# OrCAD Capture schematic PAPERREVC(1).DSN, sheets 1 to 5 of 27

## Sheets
1 PAGE1: title: SMART NETWORK ADC PROCESSOR (SNAP) BOARD; rev: C
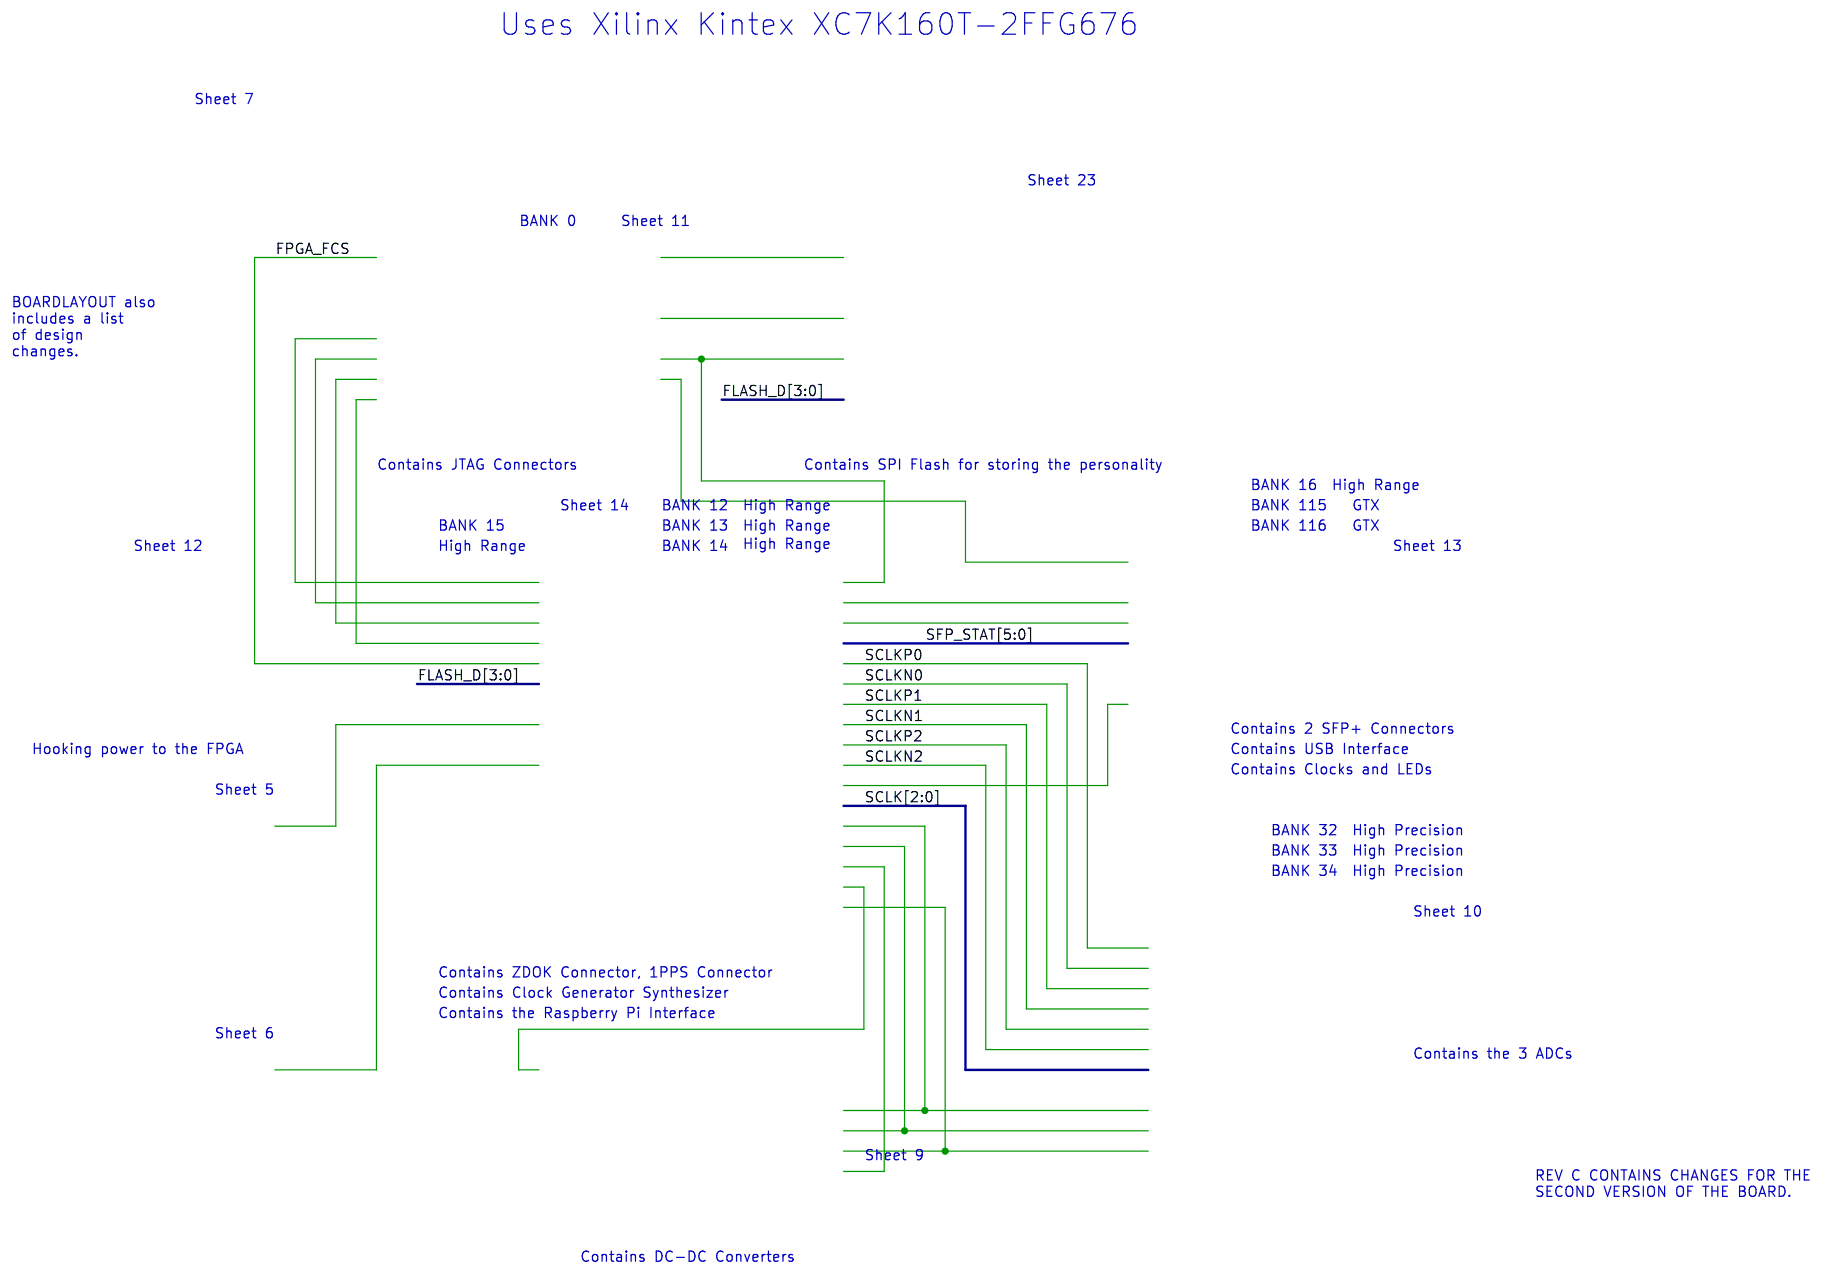
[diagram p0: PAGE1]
2 PAGE1 (2): size B; title: SNAP, JTAG and Bank 0; block FPGA0
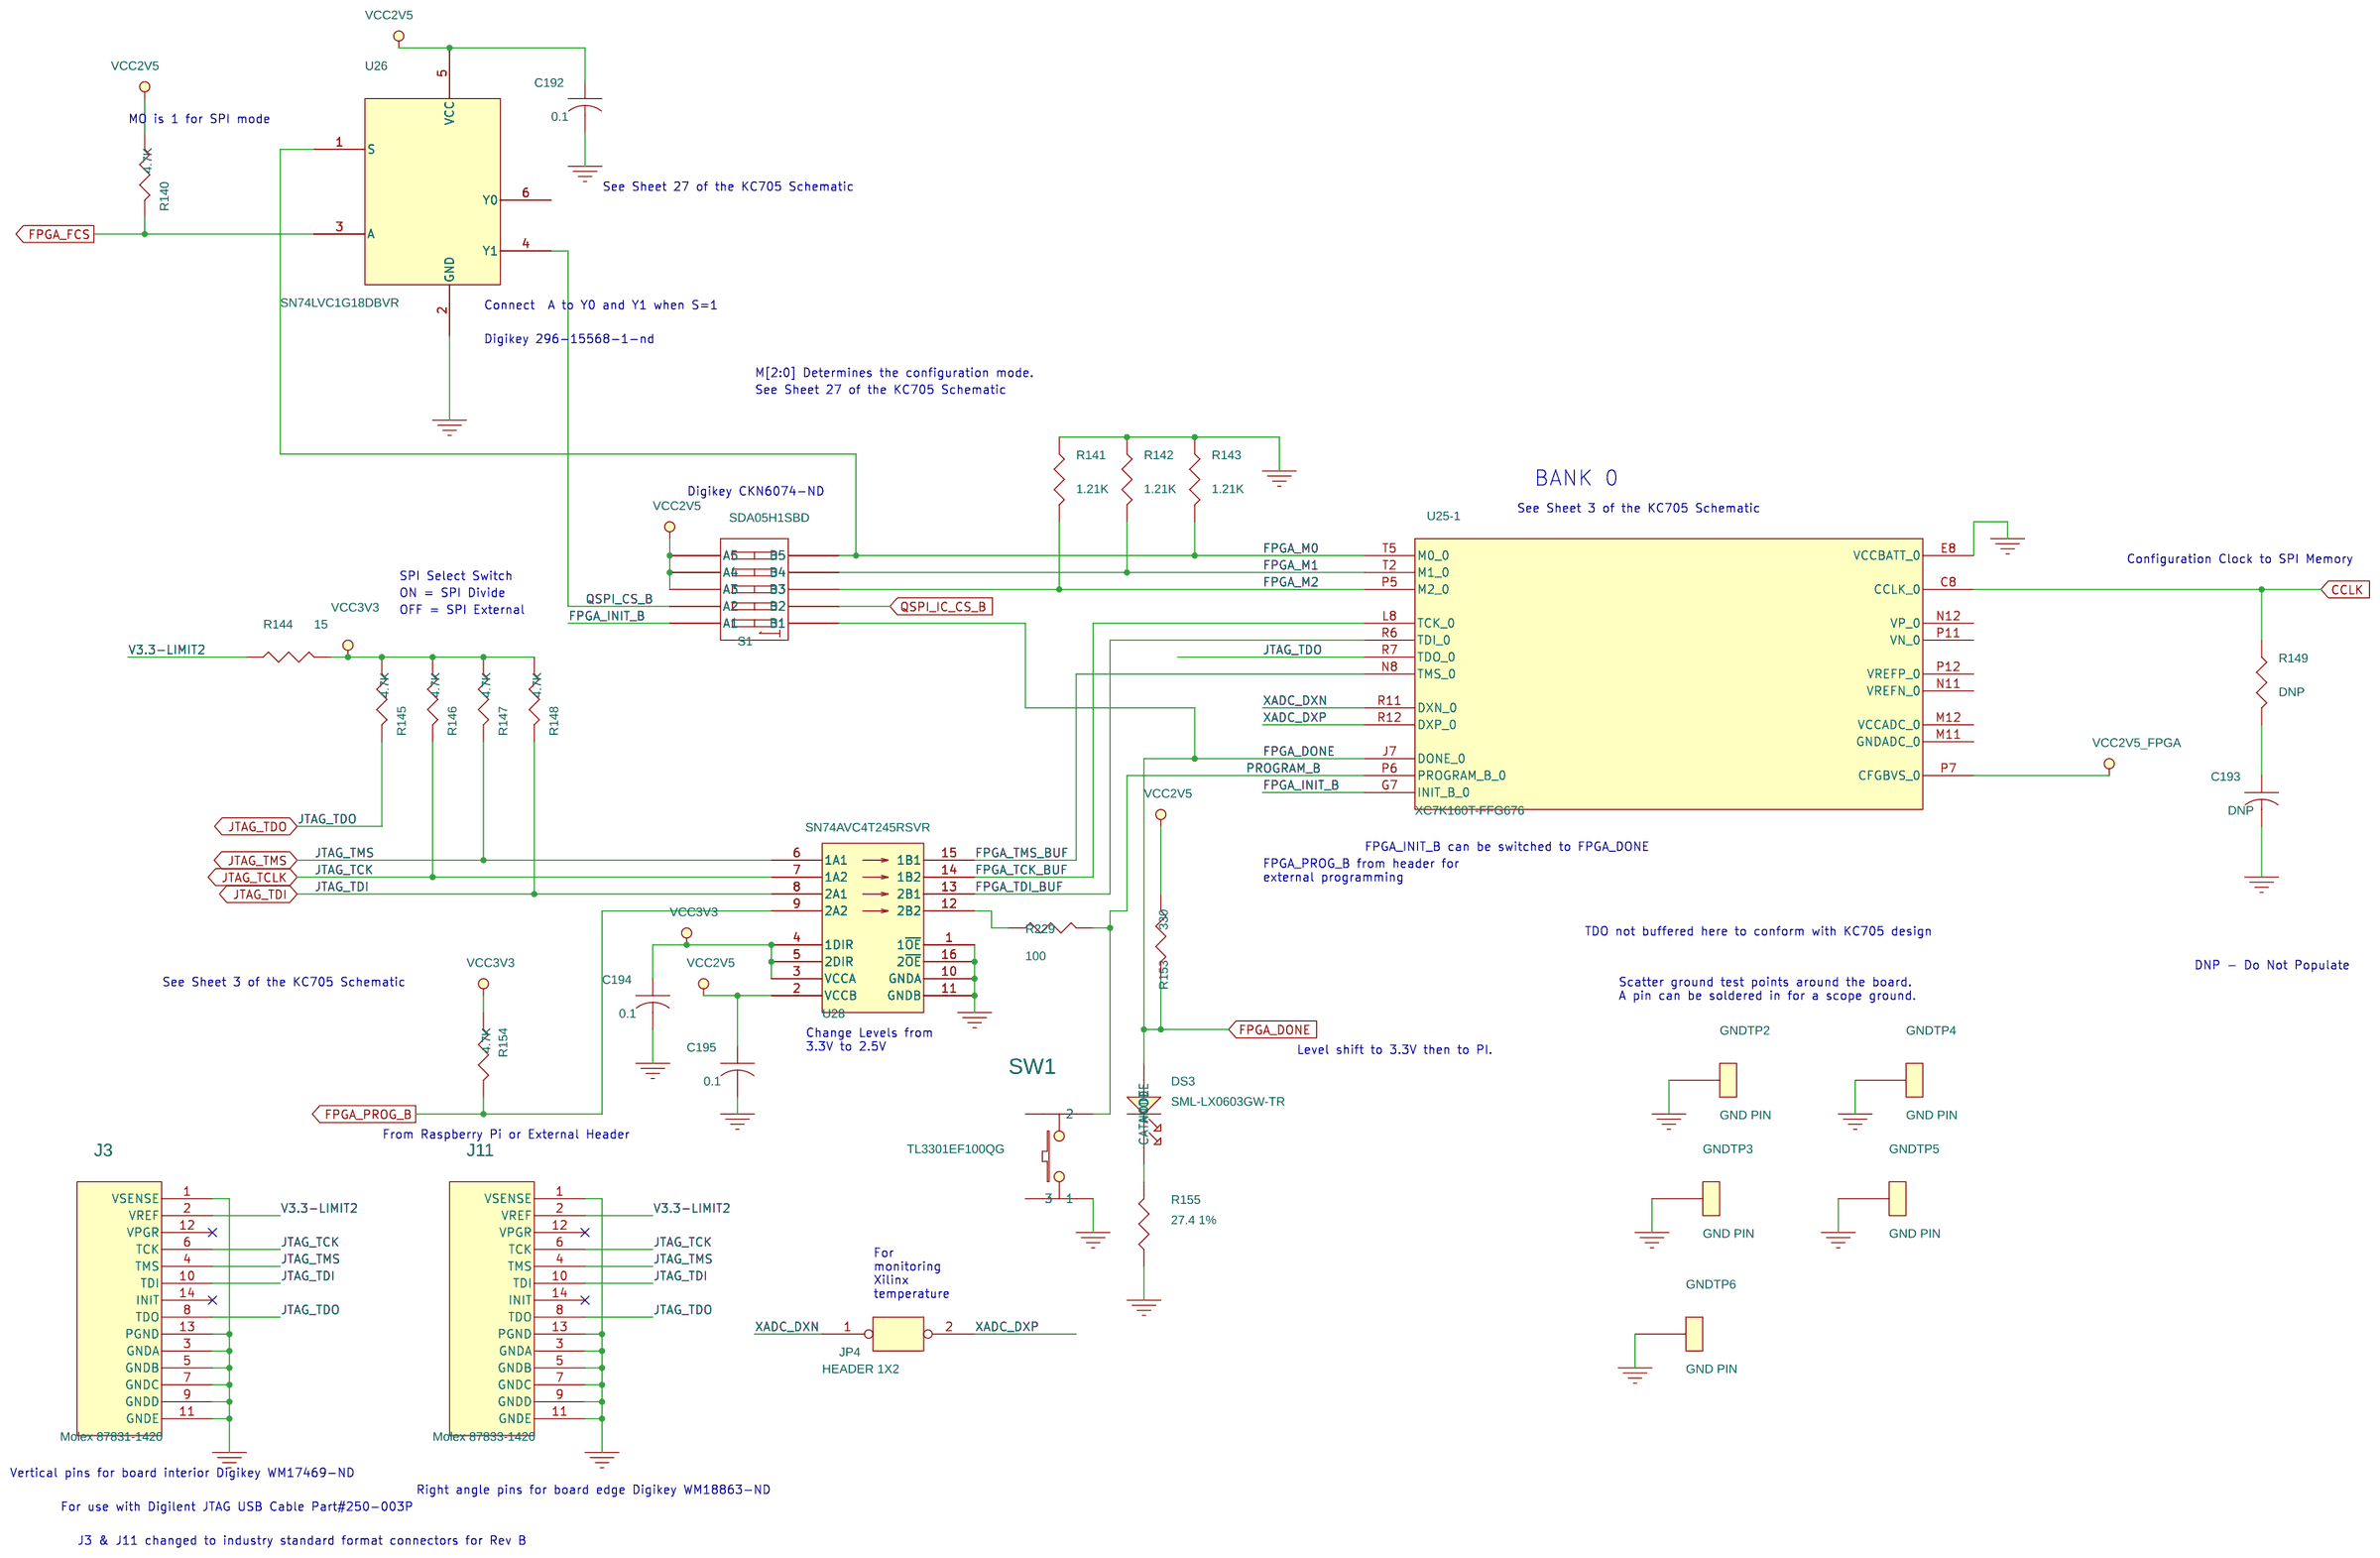
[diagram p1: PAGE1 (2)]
3 PAGE1 (3): size B; title: SNAP, A/D CONVERTERS; block FPGA32
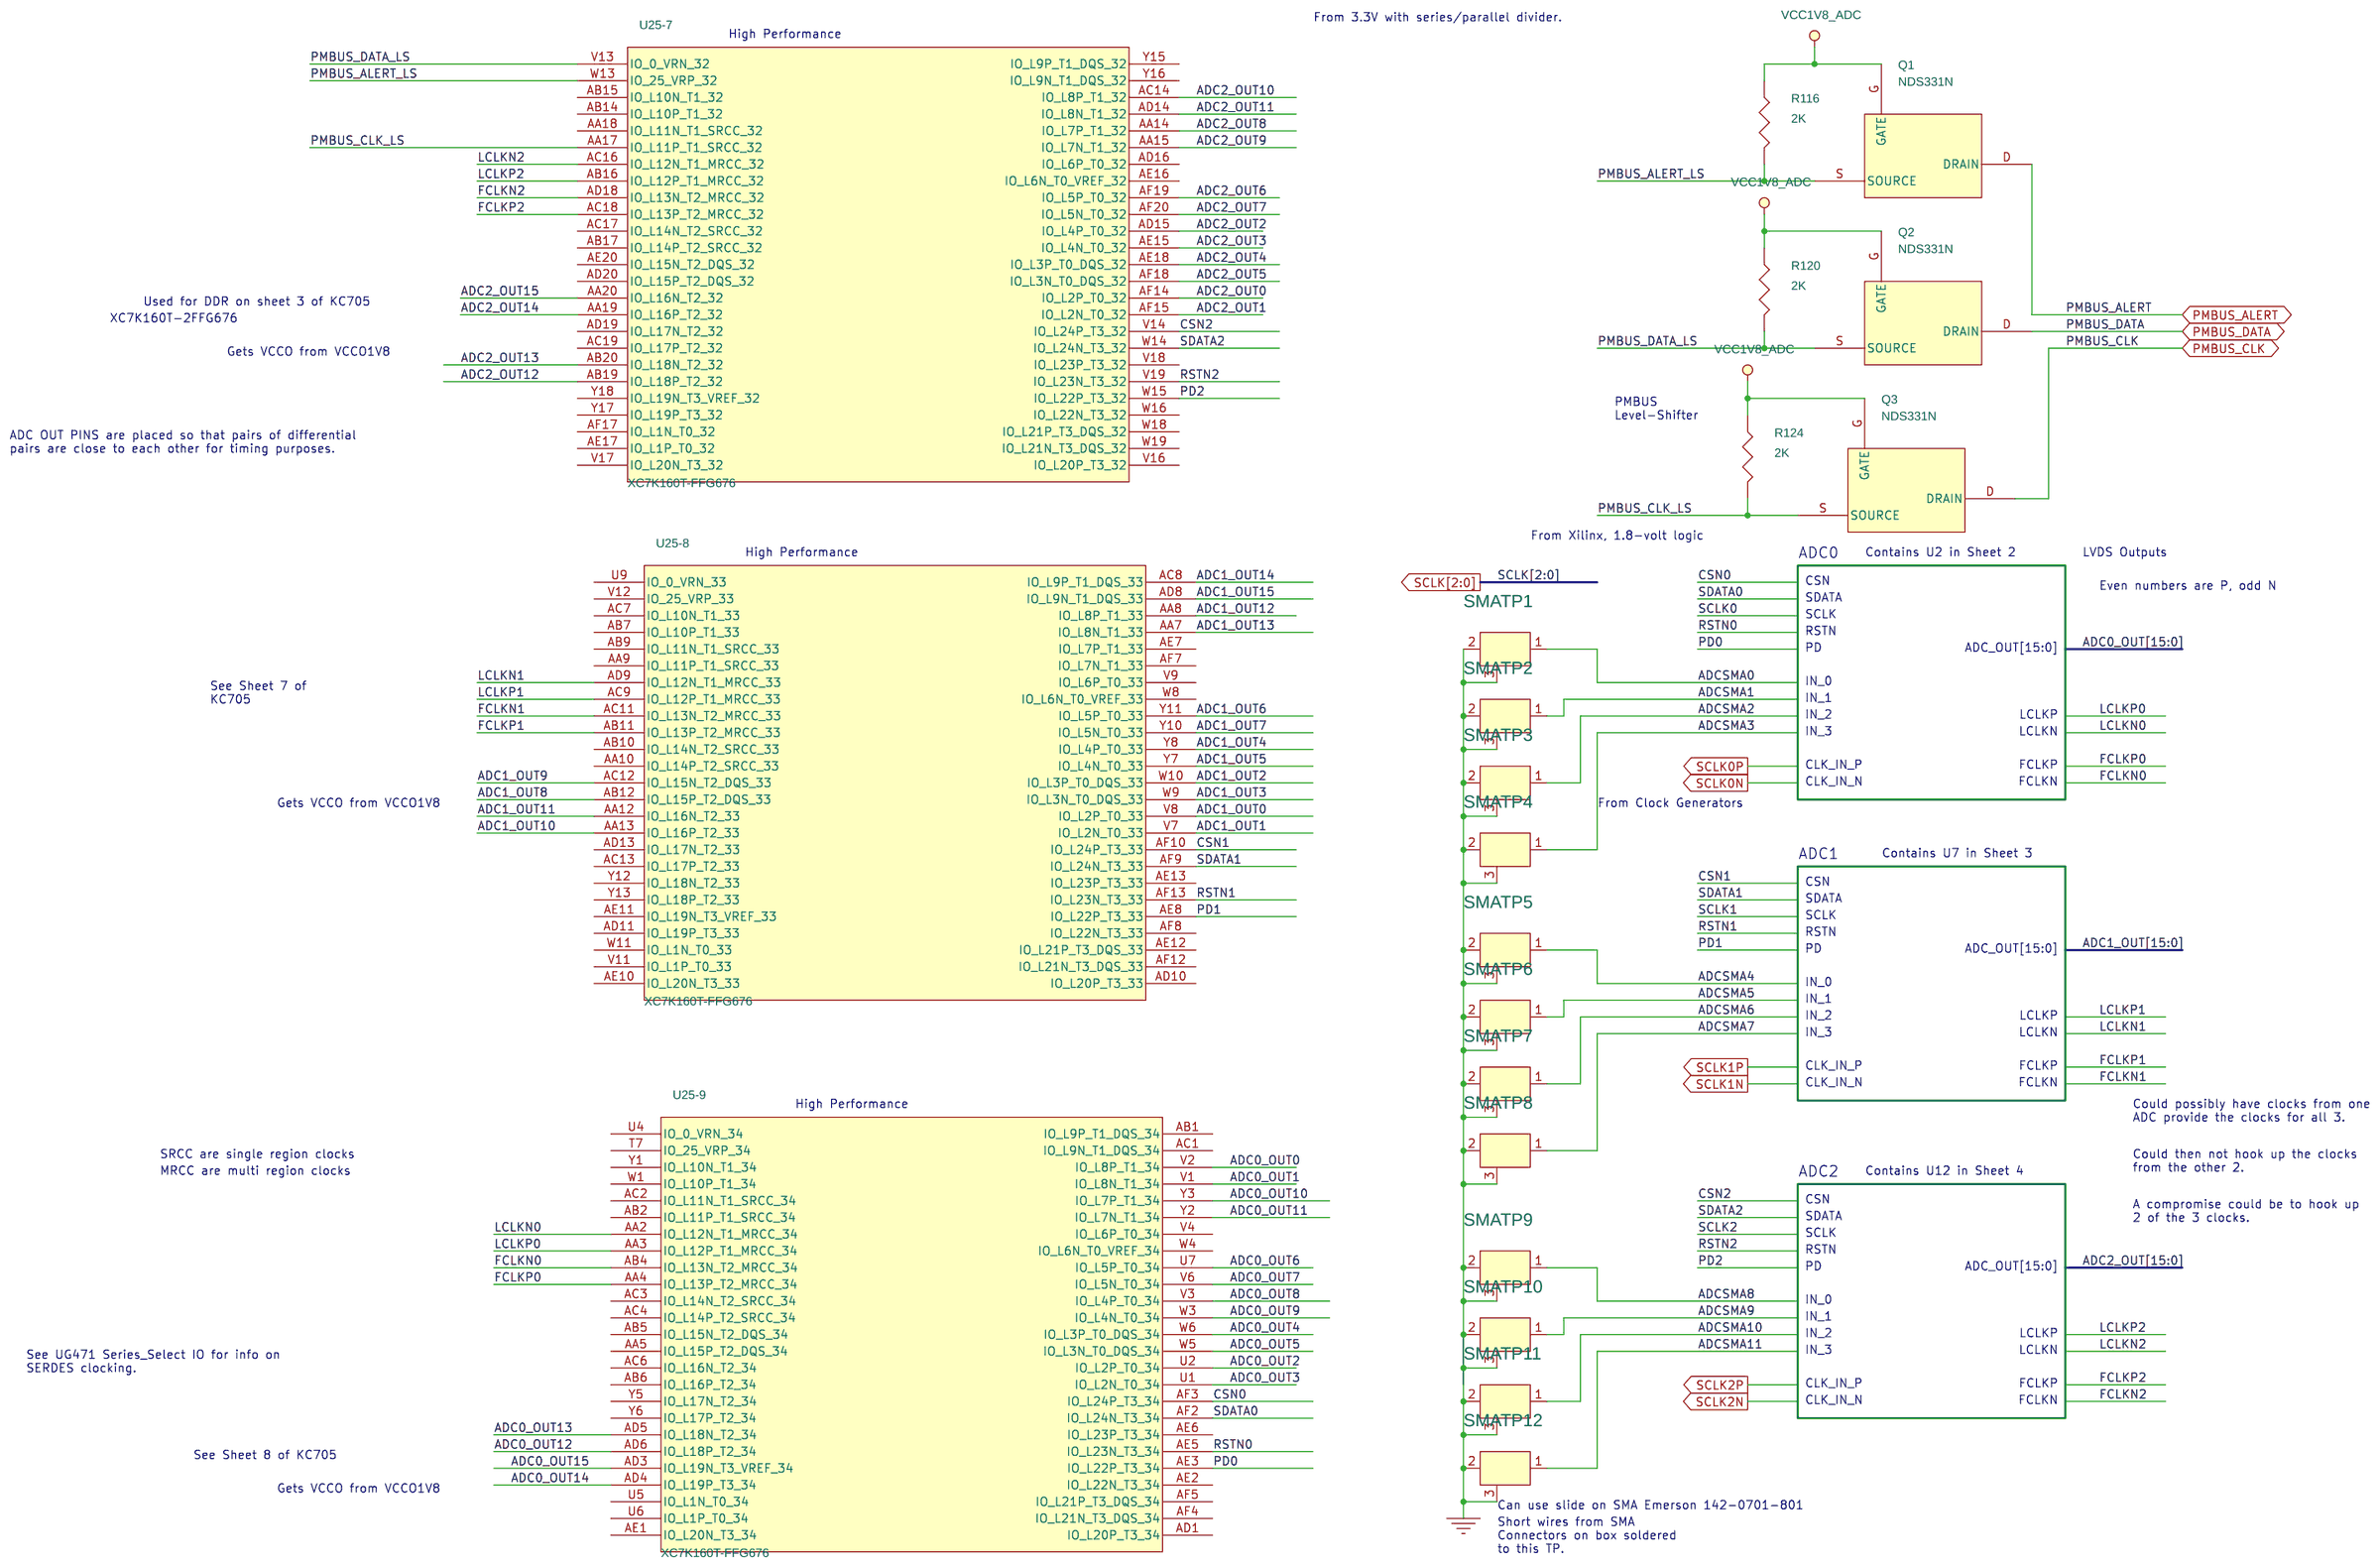
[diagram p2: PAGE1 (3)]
4 PAGE1 (4): size B; title: SNAP, ADC; block FPGA32/ADC2
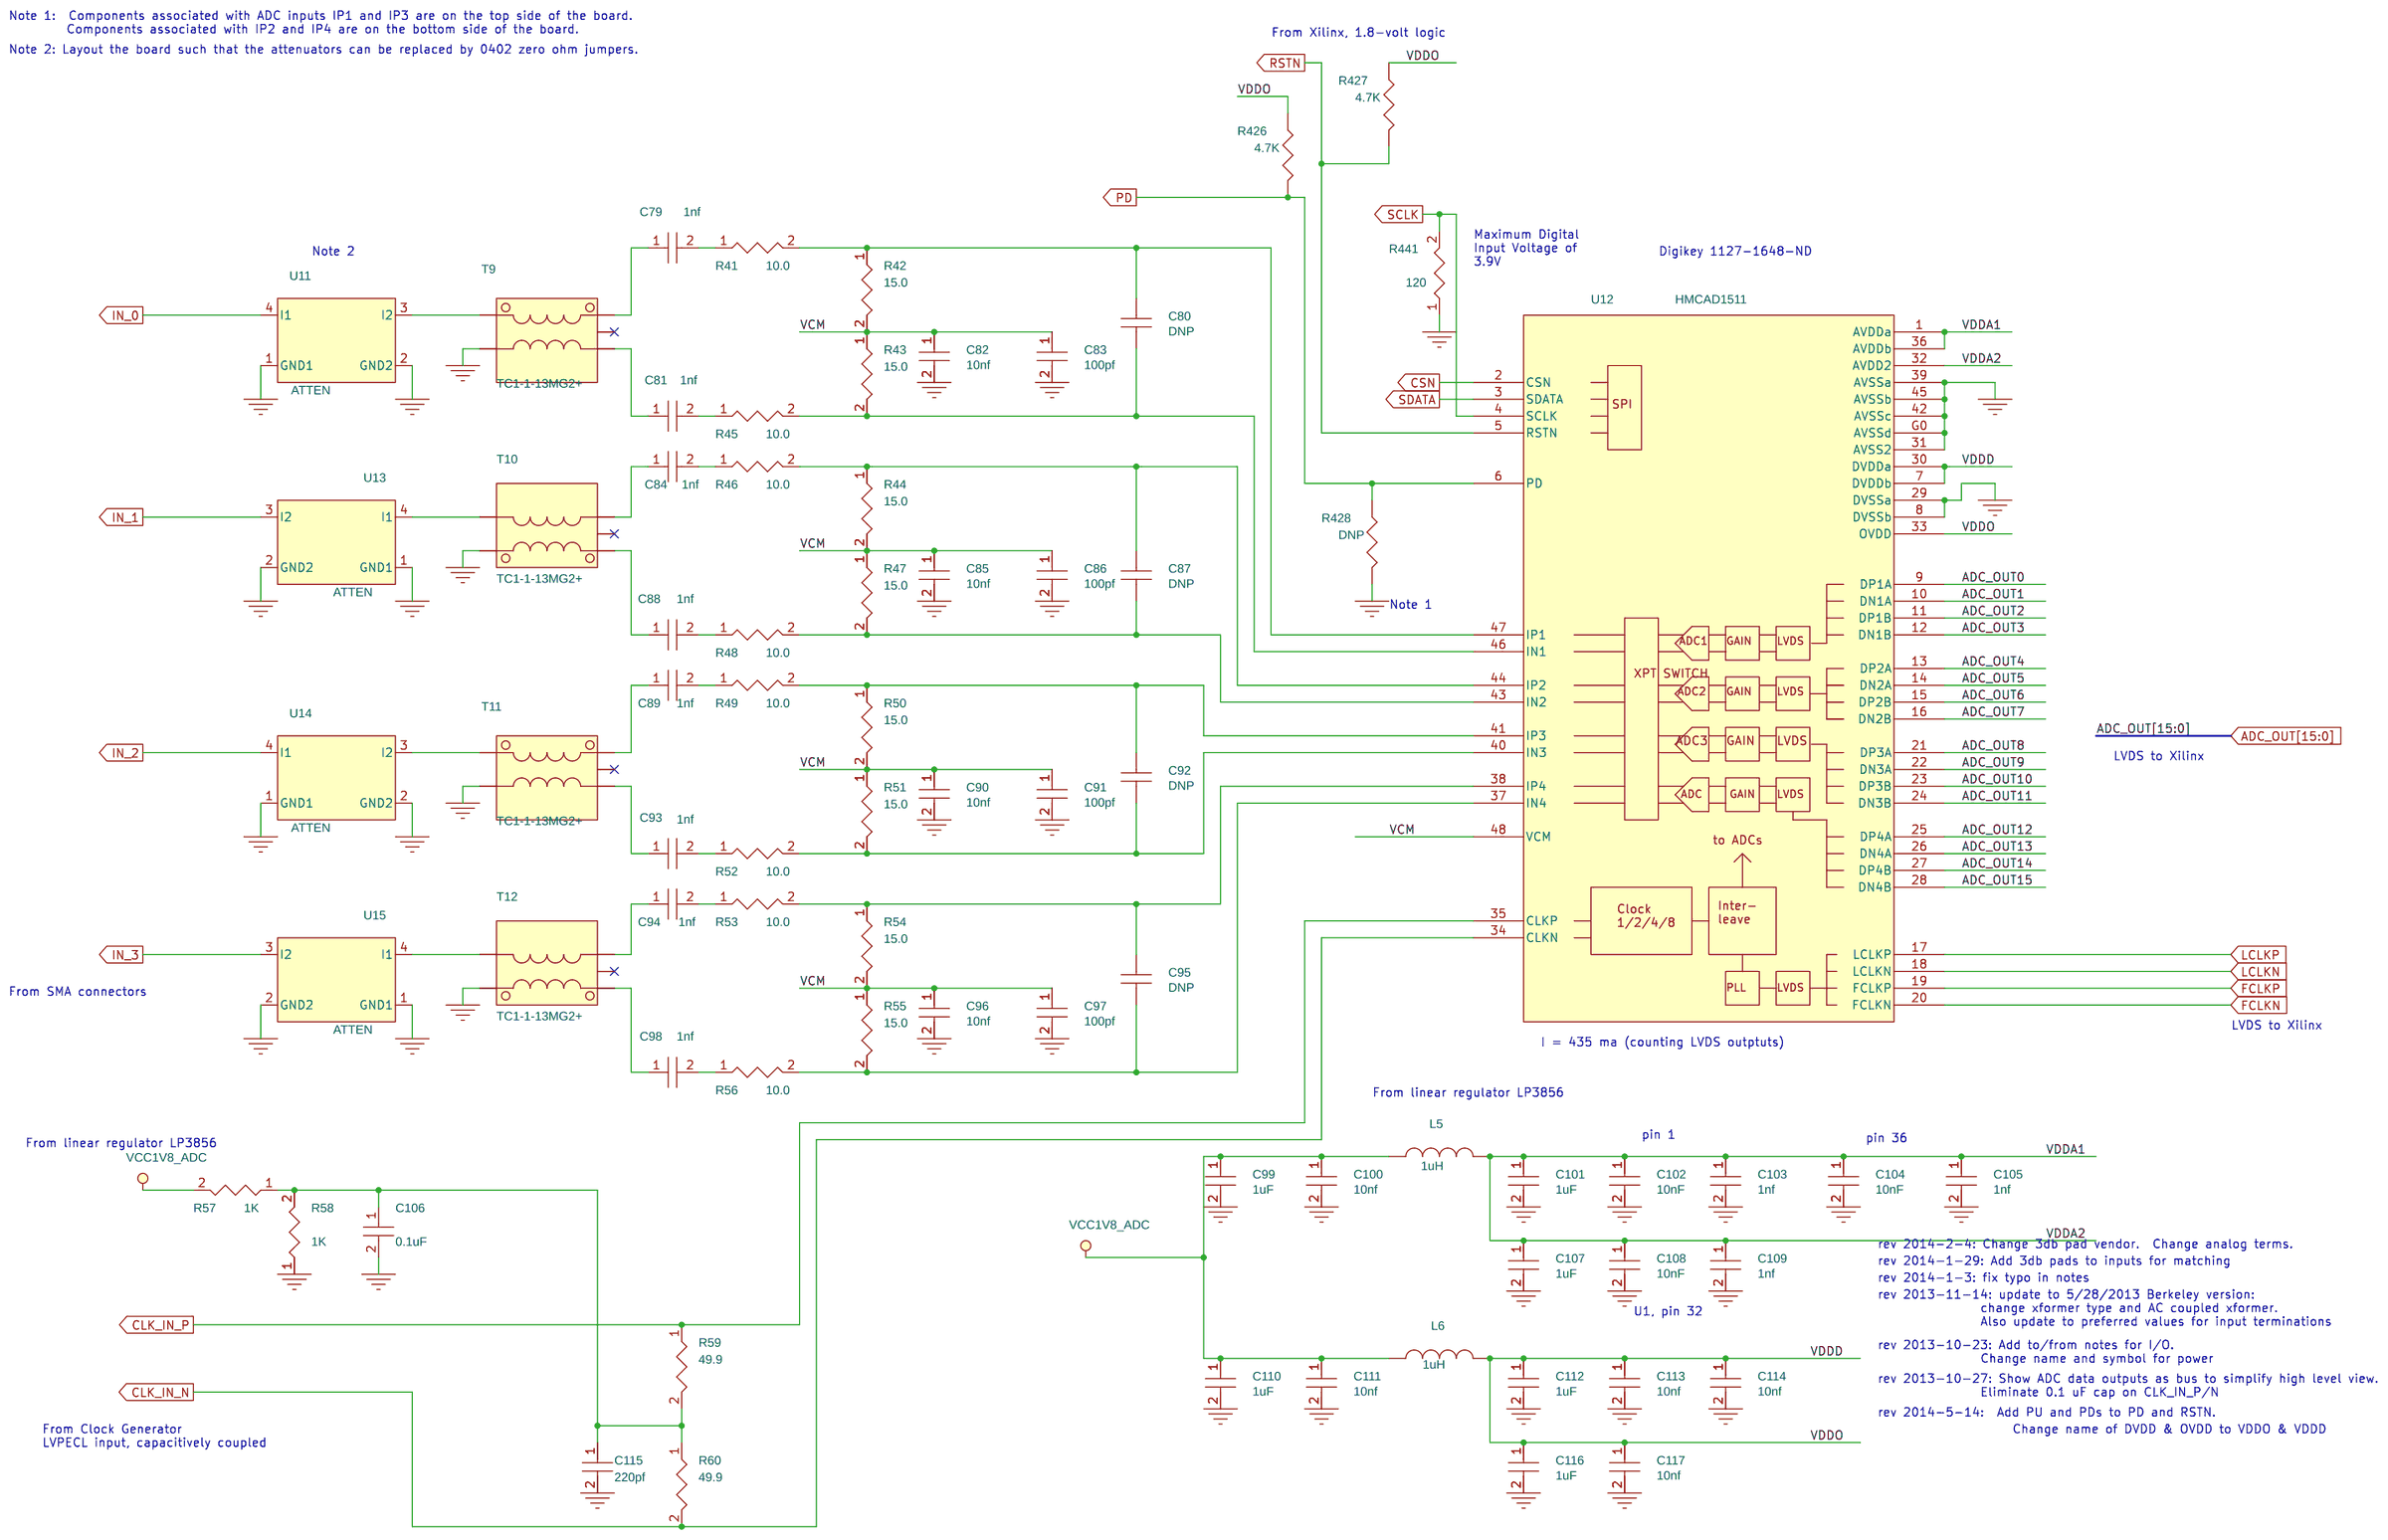
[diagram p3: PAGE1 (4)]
5 PAGE1 (5): block FPGA32/ADC0, another copy of sheet 4

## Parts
sheet PAGE1 (2)
C192  0.1  [CAPC1005X50L]
C193  DNP  [CAPC1608X90N]
C194  0.1  [CAPC1005X50L]
C195  0.1  [CAPC1005X50L]
DS3  SML-LX0603GW-TR  [LEDM180X60X60N]
GNDTP2  GND PIN  [TP107]
GNDTP3  GND PIN  [TP107]
GNDTP4  GND PIN  [TP107]
GNDTP5  GND PIN  [TP107]
GNDTP6  GND PIN  [TP107]
J3  Molex 87831-1420  [shdrv14w55p200_7x2_1665x630h-1]
J11  Molex 87833-1420  [shdrra14w55p200_7x2_1665x100-1]
JP4  HEADER 1X2  [HDRV254W64P254R1L508T254H838]
R140  4.7K  [RESC1005X35N]
R141  1.21K  [RESC1005X35N]
R142  1.21K  [RESC1005X35N]
R143  1.21K  [RESC1005X35N]
R144  15  [RESC1005X35N]
R145  4.7K  [RESC1005X35N]
R146  4.7K  [RESC1005X35N]
R147  4.7K  [RESC1005X35N]
R148  4.7K  [RESC1005X35N]
R149  DNP  [RESC1608X50N]
R153  330  [RESC1608X50N]
R154  4.7K  [RESC1005X35N]
R155  27.4 1%  [RESC1005X35N]
R229  100  [RESC1005X35N]
S1  SDA05H1SBD  [SW_SDA05H1SBD]
SW1  TL3301EF100QG  [SW_TL3301EF100QG]
U26  SN74LVC1G18DBVR  [SOT95P280X145-6N]
U28  SN74AVC4T245RSVR  [QFN40P260X180X55-16L]
sheet PAGE1 (3)
Q1  NDS331N  [SOT95P237X100-4]
Q2  NDS331N  [SOT95P237X100-4]
Q3  NDS331N  [SOT95P237X100-4]
R116  2K  [RESC1005X35N]
R120  2K  [RESC1005X35N]
R124  2K  [RESC1005X35N]
SMATP1  SMATP  [SMA_END_LAUNCH]
SMATP2  SMATP  [SMA_END_LAUNCH]
SMATP3  SMATP  [SMA_END_LAUNCH]
SMATP4  SMATP  [SMA_END_LAUNCH]
SMATP5  SMATP  [SMA_END_LAUNCH]
SMATP6  SMATP  [SMA_END_LAUNCH]
SMATP7  SMATP  [SMA_END_LAUNCH]
SMATP8  SMATP  [SMA_END_LAUNCH]
SMATP9  SMATP  [SMA_END_LAUNCH]
SMATP10  SMATP  [SMA_END_LAUNCH]
SMATP11  SMATP  [SMA_END_LAUNCH]
SMATP12  SMATP  [SMA_END_LAUNCH]
U25  XC7K160T-FFG676  [bga676c100p26x26_2700x2700x260]  (sections -1,-10,-11,-12,-13,-14,-2,-3,-4,-5,-6,-7,-8,-9)
sheet PAGE1 (4)
C79  1nf  [CAPC1005X50L]
C80  DNP  [CAPC1005X50L]
C81  1nf  [CAPC1005X50L]
C82  10nf  [CAPC1005X50L]
C83  100pf  [CAPC1005X50L]
C84  1nf  [CAPC1005X50L]
C85  10nf  [CAPC1005X50L]
C86  100pf  [CAPC1005X50L]
C87  DNP  [CAPC1005X50L]
C88  1nf  [CAPC1005X50L]
C89  1nf  [CAPC1005X50L]
C90  10nf  [CAPC1005X50L]
C91  100pf  [CAPC1005X50L]
C92  DNP  [CAPC1005X50L]
C93  1nf  [CAPC1005X50L]
C94  1nf  [CAPC1005X50L]
C95  DNP  [CAPC1005X50L]
C96  10nf  [CAPC1005X50L]
C97  100pf  [CAPC1005X50L]
C98  1nf  [CAPC1005X50L]
C99  1uF  [CAPC1608X90N]
C100  10nf  [CAPC1005X50L]
C101  1uF  [CAPC1608X90N]
C102  10nF  [CAPC1005X50L]
C103  1nf  [CAPC1005X50L]
C104  10nF  [CAPC1005X50L]
C105  1nf  [CAPC1005X50L]
C106  0.1uF  [CAPC1005X50L]
C107  1uF  [CAPC1608X90N]
C108  10nF  [CAPC1005X50L]
C109  1nf  [CAPC1005X50L]
C110  1uF  [CAPC1608X90N]
C111  10nf  [CAPC1005X50L]
C112  1uF  [CAPC1608X90N]
C113  10nf  [CAPC1005X50L]
C114  10nf  [CAPC1005X50L]
C115  220pf  [CAPC1005X50L]
C116  1uF  [CAPC1608X90N]
C117  10nf  [CAPC1005X50L]
L5  1uH  [INDM4532X340N]
L6  1uH  [INDM4532X340N]
R41  10.0  [RESC1005X35N]
R42  15.0  [RESC1005X35N]
R43  15.0  [RESC1005X35N]
R44  15.0  [RESC1005X35N]
R45  10.0  [RESC1005X35N]
R46  10.0  [RESC1005X35N]
R47  15.0  [RESC1005X35N]
R48  10.0  [RESC1005X35N]
R49  10.0  [RESC1005X35N]
R50  15.0  [RESC1005X35N]
R51  15.0  [RESC1005X35N]
R52  10.0  [RESC1005X35N]
R53  10.0  [RESC1005X35N]
R54  15.0  [RESC1005X35N]
R55  15.0  [RESC1005X35N]
R56  10.0  [RESC1005X35N]
R57  1K  [RESC1005X35N]
R58  1K  [RESC1005X35N]
R59  49.9  [RESC1005X35N]
R60  49.9  [RESC1005X35N]
R426  4.7K  [RESC1005X35N]
R427  4.7K  [RESC1005X35N]
R428  DNP  [RESC1005X35N]
R441  120  [RESC1608X50N]
T9  TC1-1-13MG2+  [XFMR_TC1-1-13MG2]
T10  TC1-1-13MG2+  [XFMR_TC1-1-13MG2]
T11  TC1-1-13MG2+  [XFMR_TC1-1-13MG2]
T12  TC1-1-13MG2+  [XFMR_TC1-1-13MG2]
U11  ATTEN  [RESCAF65P100X100X45-4N]
U12  HMCAD1511  [QFN50P700X700X100-49T540X540L]
U13  ATTEN  [RESCAF65P100X100X45-4N]
U14  ATTEN  [RESCAF65P100X100X45-4N]
U15  ATTEN  [RESCAF65P100X100X45-4N]
sheet PAGE1 (5)
C1  1nf  [CAPC1005X50L]
C2  DNP  [CAPC1005X50L]
C3  1nf  [CAPC1005X50L]
C4  10nf  [CAPC1005X50L]
C5  100pf  [CAPC1005X50L]
C6  1nf  [CAPC1005X50L]
C7  10nf  [CAPC1005X50L]
C8  100pf  [CAPC1005X50L]
C9  DNP  [CAPC1005X50L]
C10  1nf  [CAPC1005X50L]
C11  1nf  [CAPC1005X50L]
C12  10nf  [CAPC1005X50L]
C13  100pf  [CAPC1005X50L]
C14  DNP  [CAPC1005X50L]
C15  1nf  [CAPC1005X50L]
C16  1nf  [CAPC1005X50L]
C17  DNP  [CAPC1005X50L]
C18  10nf  [CAPC1005X50L]
C19  100pf  [CAPC1005X50L]
C20  1nf  [CAPC1005X50L]
C21  1uF  [CAPC1608X90N]
C22  10nf  [CAPC1005X50L]
C23  1uF  [CAPC1608X90N]
C24  10nF  [CAPC1005X50L]
C25  1nf  [CAPC1005X50L]
C26  10nF  [CAPC1005X50L]
C27  1nf  [CAPC1005X50L]
C28  0.1uF  [CAPC1005X50L]
C29  1uF  [CAPC1608X90N]
C30  10nF  [CAPC1005X50L]
C31  1nf  [CAPC1005X50L]
C32  1uF  [CAPC1608X90N]
C33  10nf  [CAPC1005X50L]
C34  1uF  [CAPC1608X90N]
C35  10nf  [CAPC1005X50L]
C36  10nf  [CAPC1005X50L]
C37  220pf  [CAPC1005X50L]
C38  1uF  [CAPC1608X90N]
C39  10nf  [CAPC1005X50L]
L1  1uH  [INDM4532X340N]
L2  1uH  [INDM4532X340N]
R1  10.0  [RESC1005X35N]
R2  15.0  [RESC1005X35N]
R3  15.0  [RESC1005X35N]
R4  15.0  [RESC1005X35N]
R5  10.0  [RESC1005X35N]
R6  10.0  [RESC1005X35N]
R7  15.0  [RESC1005X35N]
R8  10.0  [RESC1005X35N]
R9  10.0  [RESC1005X35N]
R10  15.0  [RESC1005X35N]
R11  15.0  [RESC1005X35N]
R12  10.0  [RESC1005X35N]
R13  10.0  [RESC1005X35N]
R14  15.0  [RESC1005X35N]
R15  15.0  [RESC1005X35N]
R16  10.0  [RESC1005X35N]
R17  1K  [RESC1005X35N]
R18  1K  [RESC1005X35N]
R19  49.9  [RESC1005X35N]
R20  49.9  [RESC1005X35N]
R420  4.7K  [RESC1005X35N]
R421  4.7K  [RESC1005X35N]
R422  DNP  [RESC1005X35N]
R439  120  [RESC1608X50N]
T1  TC1-1-13MG2+  [XFMR_TC1-1-13MG2]
T2  TC1-1-13MG2+  [XFMR_TC1-1-13MG2]
T3  TC1-1-13MG2+  [XFMR_TC1-1-13MG2]
T4  TC1-1-13MG2+  [XFMR_TC1-1-13MG2]
U1  ATTEN  [RESCAF65P100X100X45-4N]
U2  HMCAD1511  [QFN50P700X700X100-49T540X540L]
U3  ATTEN  [RESCAF65P100X100X45-4N]
U4  ATTEN  [RESCAF65P100X100X45-4N]
U5  ATTEN  [RESCAF65P100X100X45-4N]

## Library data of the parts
C192-C195 = CAP_0
DS3 = LED_4
GNDTP2-GNDTP6 = TEST_POINT
J3 J11 = HEADER_6x2_SM_26: COMPHEIGHT: 0.000; DECOUPLER: NO; MEMORY: NO
JP4 = HEADER_2X2_4
R140 R145-R148 R153-R155 R229 = RESISTOR_0: COMPHEIGHT: 0.000; DECOUPLER: NO; MEMORY: NO; PRECISION: 5%
R141-R143 = RESISTOR_0
R144 = RESISTOR_0: COMPHEIGHT: 0.000; DECOUPLER: NO; MEMORY: NO
R149 = RESISTOR_2
S1 = SW_DIP-5
SW1 = SW_PUSHBUTTON-SPST-2: COMPHEIGHT: 0.000; DECOUPLER: NO; MEMORY: NO
U26 = XC17256L_5
U28 = SN74LVC244A_SO_18: COMPHEIGHT: 0.000; DECOUPLER: NO; MEMORY: NO
Q1 = XC17256L_18
Q2 = XC17256L_19
Q3 = XC17256L_20
R116 R120 R124 = RESISTOR_0: COMPHEIGHT: 0.000; DECOUPLER: NO; MEMORY: NO; POWER: 1/16W; PRECISION: 1%
SMATP1-SMATP12 = HEADER_6x2_SM_25: COMPHEIGHT: 0.000; DECOUPLER: NO; MEMORY: NO
U25 = XC7K160T-FFG676
C1 C79 = CAP_NP_27: Digikey PN: 399-10034-6-ND; ESR: NA; Size: 0402; Temp. Coef.: NPO (COG); Tolerance: 5%; Voltage Rating: 50 V
C2 C9 C14 C17 C80 C87 C92 C95 = CAP_NP_2: ESR: NA; Size: 0402; Temp. Coef.: NPO (COG); Tolerance: 5%; Voltage Rating: 50 V
C3 C81 = CAP_NP_28: Digikey PN: 399-10034-6-ND; ESR: NA; Size: 0402; Temp. Coef.: NPO (COG); Tolerance: 5%; Voltage Rating: 50 V
C4 C7 C12 C18 C82 C85 C90 C96 = CAP_NP_35: Digikey PN: 399-3066-6-ND; ESR: NA; Size: 0402; Temp. Coef.: X7R; Tolerance: 10%; Voltage Rating: 25 V
C5 C8 C13 C19 C83 C86 C91 C97 = CAP_NP_36: Digikey PN: 399-1022-6-ND; ESR: NA; Size: 0402; Temp. Coef.: NPO (COG); Tolerance: 5%; Voltage Rating: 50 V
C6 C84 = CAP_NP_29: Digikey PN: 399-10034-6-ND; ESR: NA; Size: 0402; Temp. Coef.: NPO (COG); Tolerance: 5%; Voltage Rating: 50 V
C10 C88 = CAP_NP_30: Digikey PN: 399-10034-6-ND; ESR: NA; Size: 0402; Temp. Coef.: NPO (COG); Tolerance: 5%; Voltage Rating: 50 V
C11 C89 = CAP_NP_31: Digikey PN: 399-10034-6-ND; ESR: NA; Size: 0402; Temp. Coef.: NPO (COG); Tolerance: 5%; Voltage Rating: 50 V
C15 C93 = CAP_NP_32: Digikey PN: 399-10034-6-ND; ESR: NA; Size: 0402; Temp. Coef.: NPO (COG); Tolerance: 5%; Voltage Rating: 50 V
C16 C94 = CAP_NP_33: Digikey PN: 399-10034-6-ND; ESR: NA; Size: 0402; Temp. Coef.: NPO (COG); Tolerance: 5%; Voltage Rating: 50 V
C20 C98 = CAP_NP_34: Digikey PN: 399-10034-6-ND; ESR: NA; Size: 0402; Temp. Coef.: NPO (COG); Tolerance: 5%; Voltage Rating: 50 V
C21 C99 = CAP_NP_5: Digikey PN: 399-3118-6-ND; Size: 0603; Temp. Coef.: X5R; Tolerance: 10%; Voltage Rating: 10V
C22 C100 = CAP_NP_6: Digikey PN: 399-3066-6-ND; ESR: NA; Size: 0402; Temp. Coef.: X7R; Tolerance: 10%; Voltage Rating: 25 V
C23 C101 = CAP_NP_9: Digikey PN: 399-3118-6-ND; Size: 0603; Temp. Coef.: X5R; Tolerance: 10%; Voltage Rating: 10V
C24 C102 = CAP_NP_10: Digikey PN: 399-3066-6-ND; ESR: NA; Size: 0402; Temp. Coef.: X7R; Tolerance: 10%; Voltage Rating: 25 V
C25 C103 = CAP_NP_11: Digikey PN: 399-1032-1-ND; Size: 0402; Temp. Coef.: X7R; Tolerance: 10%; Voltage Rating: 25 V
C26 C104 = CAP_NP_12: Digikey PN: 399-3066-6-ND; ESR: NA; Size: 0402; Temp. Coef.: X7R; Tolerance: 10%; Voltage Rating: 25 V
C27 C105 = CAP_NP_13: Digikey PN: 399-1032-1-ND; Size: 0402; Temp. Coef.: X7R; Tolerance: 10%; Voltage Rating: 25 V
C28 C106 = CAP_NP_23: ESR: NA; Size: 0402; Temp. Coef.: X5R; Tolerance: 10%; Voltage Rating: 10 V
C29 C107 = CAP_NP_14: Digikey PN: 399-3118-6-ND; Size: 0603; Temp. Coef.: X5R; Tolerance: 10%; Voltage Rating: 10V
C30 C108 = CAP_NP_15: Digikey PN: 399-3066-6-ND; ESR: NA; Size: 0402; Temp. Coef.: X7R; Tolerance: 10%; Voltage Rating: 25 V
C31 C109 = CAP_NP_0: Digikey PN: 399-1032-1-ND; Size: 0402; Temp. Coef.: X7R; Tolerance: 10%; Voltage Rating: 25 V
C32 C110 = CAP_NP_7: Digikey PN: 399-3118-6-ND; Size: 0603; Temp. Coef.: X5R; Tolerance: 10%; Voltage Rating: 10V
C33 C111 = CAP_NP_8: Digikey PN: 399-3066-6-ND; ESR: NA; Size: 0402; Temp. Coef.: X7R; Tolerance: 10%; Voltage Rating: 25 V
C34 C112 = CAP_NP_17: Digikey PN: 399-3118-6-ND; Size: 0603; Temp. Coef.: X5R; Tolerance: 10%; Voltage Rating: 10V
C35 C113 = CAP_NP_18: Digikey PN: 399-3066-6-ND; ESR: NA; Size: 0402; Temp. Coef.: X7R; Tolerance: 10%; Voltage Rating: 25 V
C36 C114 = CAP_NP_19: Digikey PN: 399-3066-6-ND; ESR: NA; Size: 0402; Temp. Coef.: X7R; Tolerance: 10%; Voltage Rating: 25 V
C37 C115 = CAP_NP_22: Digikey PN: 399-7776-6-ND; ESR: NA; Size: 0402; Temp. Coef.: NPO; Tolerance: 5%; Voltage Rating: 50 V
C38 C116 = CAP_NP_20: Digikey PN: 399-3118-6-ND; Size: 0603; Temp. Coef.: X5R; Tolerance: 10%; Voltage Rating: 10V
C39 C117 = CAP_NP_21: Digikey PN: 399-3066-6-ND; ESR: NA; Size: 0402; Temp. Coef.: X7R; Tolerance: 10%; Voltage Rating: 25 V
L1 L2 L5 L6 = INDUCTOR: Current Rating: 1.05 A; DC Resistance: 0.11 ohms; Digikey PN: NLC453232T-1R0K-PF; Part No.: NLC453232T-150K-PF; Size: 1812; Tolerance: 10%; Vendor: TDK
R1 R5 R6 R8 R9 R12 R13 R16 R41 R45 R46 R48 R49 R52 R53 R56 = RESISTOR_SM_10: Digikey PN: 311-33.0LRDKR-ND; Power Rating: 1/16 W; Size: 0402; Temp. Coef.: +/- 100 PPM; Tolerance: 1%
R2 R4 R10 R14 R42 R44 R50 R54 = RESISTOR_SM_10: Digikey PN: 311-36.0LRDKR-ND; Power Rating: 1/16 W; Size: 0402; Temp. Coef.: +/- 100 PPM; Tolerance: 1%
R3 R7 R11 R15 R43 R47 R51 R55 = RESISTOR_SM_12: Digikey PN: 311-36.0LRDKR-ND; Power Rating: 1/16 W; Size: 0402; Temp. Coef.: +/- 100 PPM; Tolerance: 1%
R17 R57 = RESISTOR_SM_4: Digikey PN: 311-1.00KLRCT-ND; Power Rating: 1/10 W; Size: 0402; Temp. Coef.: +/- 100 PPM; Tolerance: 1%
R18 R58 = RESISTOR_SM_1: Digikey PN: 311-1.00KLRCT-ND; Power Rating: 1/10 W; Size: 0402; Temp. Coef.: +/- 100 PPM; Tolerance: 1%
R19 R59 = RESISTOR_SM_20: Digikey PN: 311-49.9LRDKR-ND; Power Rating: 1/10 W; Size: 0402; Temp. Coef.: +/- 100 PPM; Tolerance: 1%
R20 R60 = RESISTOR_SM_21: Digikey PN: 311-49.9LRDKR-ND; Power Rating: 1/10 W; Size: 0402; Temp. Coef.: +/- 100 PPM; Tolerance: 1%
R420-R422 R426-R428 = RESISTOR_0: COMPHEIGHT: 0.000; DECOUPLER: NO; MEMORY: NO; POWER: 1/10W; PRECISION: 1%
R439 R441 = RESISTOR_SM_1: Power Rating: 1/10 W; Size: 0603; Temp. Coef.: +/- 100 PPM; Tolerance: 1%
T1-T4 T9-T12 = TC1-1-13MG2+
U1 U3-U5 U11 U13-U15 = ATTEN
U2 U12 = HMCAD1511

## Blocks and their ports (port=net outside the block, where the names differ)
FPGA32/ADC1 = schematic ADC, on sheet PAGE1: CSN=FPGA32/CSN1, SDATA=FPGA32/SDATA1, SCLK=SCLK1, RSTN=FPGA32/RSTN1, PD=FPGA32/PD1, IN_0=FPGA32/ADCSMA4, IN_1=FPGA32/ADCSMA5, IN_2=FPGA32/ADCSMA6, IN_3=FPGA32/ADCSMA7, LCLKP=FPGA32/LCLKP1, LCLKN=FPGA32/LCLKN1, FCLKP=FPGA32/FCLKP1, FCLKN=FPGA32/FCLKN1, ADC_OUT[15:0]=ADC1_OUT[15:0], CLK_IN_P=SCLKP1, CLK_IN_N=SCLKN1
FPGA32/ADC2 = schematic ADC, on sheet PAGE1: CSN=FPGA32/CSN2, SDATA=FPGA32/SDATA2, SCLK=SCLK2, RSTN=FPGA32/RSTN2, PD=FPGA32/PD2, IN_0=FPGA32/ADCSMA8, IN_1=FPGA32/ADCSMA9, IN_2=FPGA32/ADCSMA10, IN_3=FPGA32/ADCSMA11, LCLKP=FPGA32/LCLKP2, LCLKN=FPGA32/LCLKN2, FCLKP=FPGA32/FCLKP2, FCLKN=FPGA32/FCLKN2, ADC_OUT[15:0]=ADC2_OUT[15:0], CLK_IN_P=SCLKP2, CLK_IN_N=SCLKN2
FPGA32/ADC0 = schematic ADC, on sheet PAGE1: CSN=FPGA32/CSN0, SDATA=FPGA32/SDATA0, SCLK=SCLK0, RSTN=FPGA32/RSTN0, PD=FPGA32/PD0, IN_0=FPGA32/ADCSMA0, IN_1=FPGA32/ADCSMA1, IN_2=FPGA32/ADCSMA2, IN_3=FPGA32/ADCSMA3, LCLKP=FPGA32/LCLKP0, LCLKN=FPGA32/LCLKN0, FCLKP=FPGA32/FCLKP0, FCLKN=FPGA32/FCLKN0, ADC_OUT[15:0]=ADC0_OUT[15:0], CLK_IN_P=SCLKP0, CLK_IN_N=SCLKN0

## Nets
FPGA0/V3.3-LIMIT2: J3.2(VREF) J11.2(VREF) R144.2
FPGA32/ADC0/VDDA1: C23.1 C24.1 C25.1 C26.1 C27.1 C29.1 C30.1 C31.1 L1.2 U2.1(AVDDa) U2.32(AVDD2) U2.36(AVDDb)
FPGA32/ADC0/VDDD: C34.1 C35.1 C36.1 C38.1 C39.1 L2.2 R420.1 R421.1 U2.7(DVDDb) U2.30(DVDDa) U2.33(OVDD)
FPGA32/ADC2/VDDA1: C101.1 C102.1 C103.1 C104.1 C105.1 C107.1 C108.1 C109.1 L5.2 U12.1(AVDDa) U12.32(AVDD2) U12.36(AVDDb)
FPGA32/ADC2/VDDD: C112.1 C113.1 C114.1 C116.1 C117.1 L6.2 R426.1 R427.1 U12.7(DVDDb) U12.30(DVDDa) U12.33(OVDD)
GND: C4.2 C5.2 C7.2 C8.2 C12.2 C13.2 C18.2 C19.2 C21.2 C22.2 C23.2 C24.2 C25.2 C26.2 C27.2 C28.2 C29.2 C30.2 C31.2 C32.2 C33.2 C34.2 C35.2 C36.2 C37.2 C38.2 C39.2 C82.2 C83.2 C85.2 C86.2 C90.2 C91.2 C96.2 C97.2 C99.2 C100.2 C101.2 C102.2 C103.2 C104.2 C105.2 C106.2 C107.2 C108.2 C109.2 C110.2 C111.2 C112.2 C113.2 C114.2 C115.2 C116.2 C117.2 C192.2 C193.2 C194.2 C195.2 GNDTP2.1 GNDTP3.1 GNDTP4.1 GNDTP5.1 GNDTP6.1 J3.1(VSENSE) J3.3(GNDA) J3.5(GNDB) J3.7(GNDC) J3.9(GNDD) J3.11(GNDE) J3.13(PGND) J11.1(VSENSE) J11.3(GNDA) J11.5(GNDB) J11.7(GNDC) J11.9(GNDD) J11.11(GNDE) J11.13(PGND) R18.1 R58.1 R141.1 R142.1 R143.1 R155.1 R422.2 R428.2 R439.1 R441.1 SMATP1.2 SMATP1.3 SMATP2.2 SMATP2.3 SMATP3.2 SMATP3.3 SMATP4.2 SMATP4.3 SMATP5.2 SMATP5.3 SMATP6.2 SMATP6.3 SMATP7.2 SMATP7.3 SMATP8.2 SMATP8.3 SMATP9.2 SMATP9.3 SMATP10.2 SMATP10.3 SMATP11.2 SMATP11.3 SMATP12.2 SMATP12.3 SW1.2(1) T1.4 T2.6 T3.4 T4.6 T9.4 T10.6 T11.4 T12.6 U1.1(GND1) U1.2(GND2) U2.8(DVSSb) U2.29(DVSSa) U2.31(AVSS2) U2.39(AVSSa) U2.42(AVSSc) U2.45(AVSSb) U2.G0(AVSSd) U3.1(GND1) U3.2(GND2) U4.1(GND1) U4.2(GND2) U5.1(GND1) U5.2(GND2) U11.1(GND1) U11.2(GND2) U12.8(DVSSb) U12.29(DVSSa) U12.31(AVSS2) U12.39(AVSSa) U12.42(AVSSc) U12.45(AVSSb) U12.G0(AVSSd) U13.1(GND1) U13.2(GND2) U14.1(GND1) U14.2(GND2) U15.1(GND1) U15.2(GND2) U25.E8(VCCBATT_0) U26.2(GND) U28.1(1~{OE}) U28.10(GNDA) U28.11(GNDB) U28.16(2~{OE}) ; also on sheet 6 8 9 10 11 12 13 14 15 16 17 18 19 20 21 22 23 24 25 26 27
VCC1V8_ADC: C21.1 C22.1 C32.1 C33.1 C99.1 C100.1 C110.1 C111.1 L1.1 L2.1 L5.1 L6.1 Q1.G(GATE) Q2.G(GATE) Q3.G(GATE) R17.2 R57.2 R116.1 R120.1 R124.1 ; also on sheet 6 9 23
VCC3V3: C194.1 R144.1 R145.1 R146.1 R147.1 R148.1 R154.1 U28.3(VCCA) U28.4(1DIR) U28.5(2DIR) ; also on sheet 9 11 12 13 14 15 22 27
FPGA0/FPGA_INIT_B: S1.1(A1) U25.G7(INIT_B_0)
FPGA0/FPGA_M0: R143.2 S1.6(B5) U25.T5(M0_0) U26.1(S)
FPGA0/FPGA_M1: R142.2 S1.7(B4) U25.T2(M1_0)
FPGA0/FPGA_M2: R141.2 S1.8(B3) U25.P5(M2_0)
FPGA0/FPGA_TCK_BUF: U25.L8(TCK_0) U28.14(1B2)
FPGA0/FPGA_TDI_BUF: U25.R6(TDI_0) U28.13(2B1)
FPGA0/FPGA_TMS_BUF: U25.N8(TMS_0) U28.15(1B1)
FPGA0/PROGRAM_B: R229.2 SW1.3(2) U25.P6(PROGRAM_B_0)
FPGA0/QSPI_CS_B: S1.2(A2) U26.4(Y1)
FPGA0/XADC_DXN: JP4.1 U25.R11(DXN_0)
FPGA0/XADC_DXP: JP4.2 U25.R12(DXP_0)
FPGA32/ADC0/VCM: C4.1 C5.1 C7.1 C8.1 C12.1 C13.1 C18.1 C19.1 R2.2 R3.1 R4.2 R7.1 R10.2 R11.1 R14.2 R15.1 U2.48(VCM)
FPGA32/ADC0_OUT0: U2.9(DP1A) U25.V2(IO_L8P_T1_34)
FPGA32/ADC0_OUT1: U2.10(DN1A) U25.V1(IO_L8N_T1_34)
FPGA32/ADC0_OUT2: U2.11(DP1B) U25.U2(IO_L2P_T0_34)
FPGA32/ADC0_OUT3: U2.12(DN1B) U25.U1(IO_L2N_T0_34)
FPGA32/ADC0_OUT4: U2.13(DP2A) U25.W6(IO_L3P_T0_DQS_34)
FPGA32/ADC0_OUT5: U2.14(DN2A) U25.W5(IO_L3N_T0_DQS_34)
FPGA32/ADC0_OUT6: U2.15(DP2B) U25.U7(IO_L5P_T0_34)
FPGA32/ADC0_OUT7: U2.16(DN2B) U25.V6(IO_L5N_T0_34)
FPGA32/ADC0_OUT8: U2.21(DP3A) U25.V3(IO_L4P_T0_34)
FPGA32/ADC0_OUT9: U2.22(DN3A) U25.W3(IO_L4N_T0_34)
FPGA32/ADC0_OUT10: U2.23(DP3B) U25.Y3(IO_L7P_T1_34)
FPGA32/ADC0_OUT11: U2.24(DN3B) U25.Y2(IO_L7N_T1_34)
FPGA32/ADC0_OUT12: U2.25(DP4A) U25.AD6(IO_L18P_T2_34)
FPGA32/ADC0_OUT13: U2.26(DN4A) U25.AD5(IO_L18N_T2_34)
FPGA32/ADC0_OUT14: U2.27(DP4B) U25.AD4(IO_L19P_T3_34)
FPGA32/ADC0_OUT15: U2.28(DN4B) U25.AD3(IO_L19N_T3_VREF_34)
FPGA32/ADC1_OUT0: U25.V8(IO_L2P_T0_33) ; also on sheet 6
FPGA32/ADC1_OUT1: U25.V7(IO_L2N_T0_33) ; also on sheet 6
FPGA32/ADC1_OUT2: U25.W10(IO_L3P_T0_DQS_33) ; also on sheet 6
FPGA32/ADC1_OUT3: U25.W9(IO_L3N_T0_DQS_33) ; also on sheet 6
FPGA32/ADC1_OUT4: U25.Y8(IO_L4P_T0_33) ; also on sheet 6
FPGA32/ADC1_OUT5: U25.Y7(IO_L4N_T0_33) ; also on sheet 6
FPGA32/ADC1_OUT6: U25.Y11(IO_L5P_T0_33) ; also on sheet 6
FPGA32/ADC1_OUT7: U25.Y10(IO_L5N_T0_33) ; also on sheet 6
FPGA32/ADC1_OUT8: U25.AB12(IO_L15P_T2_DQS_33) ; also on sheet 6
FPGA32/ADC1_OUT9: U25.AC12(IO_L15N_T2_DQS_33) ; also on sheet 6
FPGA32/ADC1_OUT10: U25.AA13(IO_L16P_T2_33) ; also on sheet 6
FPGA32/ADC1_OUT11: U25.AA12(IO_L16N_T2_33) ; also on sheet 6
FPGA32/ADC1_OUT12: U25.AA8(IO_L8P_T1_33) ; also on sheet 6
FPGA32/ADC1_OUT13: U25.AA7(IO_L8N_T1_33) ; also on sheet 6
FPGA32/ADC1_OUT14: U25.AC8(IO_L9P_T1_DQS_33) ; also on sheet 6
FPGA32/ADC1_OUT15: U25.AD8(IO_L9N_T1_DQS_33) ; also on sheet 6
FPGA32/ADC2/VCM: C82.1 C83.1 C85.1 C86.1 C90.1 C91.1 C96.1 C97.1 R42.2 R43.1 R44.2 R47.1 R50.2 R51.1 R54.2 R55.1 U12.48(VCM)
FPGA32/ADC2_OUT0: U12.9(DP1A) U25.AF14(IO_L2P_T0_32)
FPGA32/ADC2_OUT1: U12.10(DN1A) U25.AF15(IO_L2N_T0_32)
FPGA32/ADC2_OUT2: U12.11(DP1B) U25.AD15(IO_L4P_T0_32)
FPGA32/ADC2_OUT3: U12.12(DN1B) U25.AE15(IO_L4N_T0_32)
FPGA32/ADC2_OUT4: U12.13(DP2A) U25.AE18(IO_L3P_T0_DQS_32)
FPGA32/ADC2_OUT5: U12.14(DN2A) U25.AF18(IO_L3N_T0_DQS_32)
FPGA32/ADC2_OUT6: U12.15(DP2B) U25.AF19(IO_L5P_T0_32)
FPGA32/ADC2_OUT7: U12.16(DN2B) U25.AF20(IO_L5N_T0_32)
FPGA32/ADC2_OUT8: U12.21(DP3A) U25.AA14(IO_L7P_T1_32)
FPGA32/ADC2_OUT9: U12.22(DN3A) U25.AA15(IO_L7N_T1_32)
FPGA32/ADC2_OUT10: U12.23(DP3B) U25.AC14(IO_L8P_T1_32)
FPGA32/ADC2_OUT11: U12.24(DN3B) U25.AD14(IO_L8N_T1_32)
FPGA32/ADC2_OUT12: U12.25(DP4A) U25.AB19(IO_L18P_T2_32)
FPGA32/ADC2_OUT13: U12.26(DN4A) U25.AB20(IO_L18N_T2_32)
FPGA32/ADC2_OUT14: U12.27(DP4B) U25.AA19(IO_L16P_T2_32)
FPGA32/ADC2_OUT15: U12.28(DN4B) U25.AA20(IO_L16N_T2_32)
FPGA32/ADCSMA0: SMATP1.1 U1.4(I1)
FPGA32/ADCSMA1: SMATP2.1 U3.3(I2)
FPGA32/ADCSMA2: SMATP3.1 U4.4(I1)
FPGA32/ADCSMA3: SMATP4.1 U5.3(I2)
FPGA32/ADCSMA4: SMATP5.1 ; also on sheet 6
FPGA32/ADCSMA5: SMATP6.1 ; also on sheet 6
FPGA32/ADCSMA6: SMATP7.1 ; also on sheet 6
FPGA32/ADCSMA7: SMATP8.1 ; also on sheet 6
FPGA32/ADCSMA8: SMATP9.1 U11.4(I1)
FPGA32/ADCSMA9: SMATP10.1 U13.3(I2)
FPGA32/ADCSMA10: SMATP11.1 U14.4(I1)
FPGA32/ADCSMA11: SMATP12.1 U15.3(I2)
FPGA32/CSN0: U2.2(CSN) U25.AF3(IO_L24P_T3_34)
FPGA32/CSN1: U25.AF10(IO_L24P_T3_33) ; also on sheet 6
FPGA32/CSN2: U12.2(CSN) U25.V14(IO_L24P_T3_32)
FPGA32/FCLKN0: U2.20(FCLKN) U25.AB4(IO_L13N_T2_MRCC_34)
FPGA32/FCLKN1: U25.AC11(IO_L13N_T2_MRCC_33) ; also on sheet 6
FPGA32/FCLKN2: U12.20(FCLKN) U25.AD18(IO_L13N_T2_MRCC_32)
FPGA32/FCLKP0: U2.19(FCLKP) U25.AA4(IO_L13P_T2_MRCC_34)
FPGA32/FCLKP1: U25.AB11(IO_L13P_T2_MRCC_33) ; also on sheet 6
FPGA32/FCLKP2: U12.19(FCLKP) U25.AC18(IO_L13P_T2_MRCC_32)
FPGA32/LCLKN0: U2.18(LCLKN) U25.AA2(IO_L12N_T1_MRCC_34)
FPGA32/LCLKN1: U25.AD9(IO_L12N_T1_MRCC_33) ; also on sheet 6
FPGA32/LCLKN2: U12.18(LCLKN) U25.AC16(IO_L12N_T1_MRCC_32)
FPGA32/LCLKP0: U2.17(LCLKP) U25.AA3(IO_L12P_T1_MRCC_34)
FPGA32/LCLKP1: U25.AC9(IO_L12P_T1_MRCC_33) ; also on sheet 6
FPGA32/LCLKP2: U12.17(LCLKP) U25.AB16(IO_L12P_T1_MRCC_32)
FPGA32/PD0: R420.2 R422.1 U2.6(PD) U25.AE3(IO_L22P_T3_34)
FPGA32/PD1: U25.AE8(IO_L22P_T3_33) ; also on sheet 6
FPGA32/PD2: R426.2 R428.1 U12.6(PD) U25.W15(IO_L22P_T3_32)
FPGA32/PMBUS_ALERT_LS: Q1.S(SOURCE) R116.2 U25.W13(IO_25_VRP_32)
FPGA32/PMBUS_CLK_LS: Q3.S(SOURCE) R124.2 U25.AA17(IO_L11P_T1_SRCC_32)
FPGA32/PMBUS_DATA_LS: Q2.S(SOURCE) R120.2 U25.V13(IO_0_VRN_32)
FPGA32/RSTN0: R421.2 U2.5(RSTN) U25.AE5(IO_L23N_T3_34)
FPGA32/RSTN1: U25.AF13(IO_L23N_T3_33) ; also on sheet 6
FPGA32/RSTN2: R427.2 U12.5(RSTN) U25.V19(IO_L23N_T3_32)
FPGA32/SDATA0: U2.3(SDATA) U25.AF2(IO_L24N_T3_34)
FPGA32/SDATA1: U25.AF9(IO_L24N_T3_33) ; also on sheet 6
FPGA32/SDATA2: U12.3(SDATA) U25.W14(IO_L24N_T3_32)
FPGA_FCS: R140.2 U26.3(A) ; also on sheet 25
SCLK0: R439.2 U2.4(SCLK) ; also on sheet 25
SCLK2: R441.2 U12.4(SCLK) ; also on sheet 25
SCLKN0: R20.2 U2.34(CLKN) ; also on sheet 26
SCLKN2: R60.2 U12.34(CLKN) ; also on sheet 26
SCLKP0: R19.1 U2.35(CLKP) ; also on sheet 26
SCLKP2: R59.1 U12.35(CLKP) ; also on sheet 26
VADJ: C192.1 C195.1 R140.1 R153.1 S1.3(A3) S1.4(A4) S1.5(A5) U25.P7(CFGBVS_0) U26.5(VCC) U28.2(VCCB) ; also on sheet 9 10 11 12 13 14 15 18 23 24 25 27
FPGA0/N9863266: C193.1 R149.2
FPGA0/N9886975: DS3.C(CATHODE) R155.2
FPGA0/N10085026: R229.1 U28.12(2B2)
FPGA32/ADC0/N168454: C28.1 C37.1 R17.1 R18.2 R19.2 R20.1
FPGA32/ADC0/N168582: C17.2 R15.2 R16.2 U2.37(IN4)
FPGA32/ADC0/N168590: C17.1 R13.2 R14.1 U2.38(IP4)
FPGA32/ADC0/N168598: C14.2 R11.2 R12.2 U2.40(IN3)
FPGA32/ADC0/N168606: C14.1 R9.2 R10.1 U2.41(IP3)
FPGA32/ADC0/N168618: C9.2 R7.2 R8.2 U2.43(IN2)
FPGA32/ADC0/N168630: C9.1 R4.1 R6.2 U2.44(IP2)
FPGA32/ADC0/N168650: C2.2 R3.2 R5.2 U2.46(IN1)
FPGA32/ADC0/N168658: C2.1 R1.2 R2.1 U2.47(IP1)
FPGA32/ADC0/N168814: T1.6 U1.3(I2)
FPGA32/ADC0/N168842: T2.4 U3.4(I1)
FPGA32/ADC0/N168902: T3.6 U4.3(I2)
FPGA32/ADC0/N169034: T4.4 U5.4(I1)
FPGA32/ADC0/N169678: C1.1 T1.1
FPGA32/ADC0/N169712: C3.1 T1.3
FPGA32/ADC0/N169780: C1.2 R1.1
FPGA32/ADC0/N169792: C3.2 R5.1
FPGA32/ADC0/N169940: C6.1 T2.3
FPGA32/ADC0/N169968: C10.1 T2.1
FPGA32/ADC0/N170050: C6.2 R6.1
FPGA32/ADC0/N170062: C10.2 R8.1
FPGA32/ADC0/N170286: C11.2 R9.1
FPGA32/ADC0/N170298: C15.2 R12.1
FPGA32/ADC0/N170430: C11.1 T3.1
FPGA32/ADC0/N170484: C15.1 T3.3
FPGA32/ADC0/N170586: C16.2 R13.1
FPGA32/ADC0/N170598: C20.2 R16.1
FPGA32/ADC0/N170658: C16.1 T4.3
FPGA32/ADC0/N170734: C20.1 T4.1
FPGA32/ADC2/N168454: C106.1 C115.1 R57.1 R58.2 R59.2 R60.1
FPGA32/ADC2/N168582: C95.2 R55.2 R56.2 U12.37(IN4)
FPGA32/ADC2/N168590: C95.1 R53.2 R54.1 U12.38(IP4)
FPGA32/ADC2/N168598: C92.2 R51.2 R52.2 U12.40(IN3)
FPGA32/ADC2/N168606: C92.1 R49.2 R50.1 U12.41(IP3)
FPGA32/ADC2/N168618: C87.2 R47.2 R48.2 U12.43(IN2)
FPGA32/ADC2/N168630: C87.1 R44.1 R46.2 U12.44(IP2)
FPGA32/ADC2/N168650: C80.2 R43.2 R45.2 U12.46(IN1)
FPGA32/ADC2/N168658: C80.1 R41.2 R42.1 U12.47(IP1)
FPGA32/ADC2/N168814: T9.6 U11.3(I2)
FPGA32/ADC2/N168842: T10.4 U13.4(I1)
FPGA32/ADC2/N168902: T11.6 U14.3(I2)
FPGA32/ADC2/N169034: T12.4 U15.4(I1)
FPGA32/ADC2/N169678: C79.1 T9.1
FPGA32/ADC2/N169712: C81.1 T9.3
FPGA32/ADC2/N169780: C79.2 R41.1
FPGA32/ADC2/N169792: C81.2 R45.1
FPGA32/ADC2/N169940: C84.1 T10.3
FPGA32/ADC2/N169968: C88.1 T10.1
FPGA32/ADC2/N170050: C84.2 R46.1
FPGA32/ADC2/N170062: C88.2 R48.1
FPGA32/ADC2/N170286: C89.2 R49.1
FPGA32/ADC2/N170298: C93.2 R52.1
FPGA32/ADC2/N170430: C89.1 T11.1
FPGA32/ADC2/N170484: C93.1 T11.3
FPGA32/ADC2/N170586: C94.2 R53.1
FPGA32/ADC2/N170598: C98.2 R56.1
FPGA32/ADC2/N170658: C94.1 T12.3
FPGA32/ADC2/N170734: C98.1 T12.1
N9912452: R154.2 U28.9(2A2) ; also on sheet 24 25
N9912822: R149.1 U25.C8(CCLK_0) ; also on sheet 24
N9912826: S1.9(B2) ; also on sheet 24
N9967310: Q2.D(DRAIN) ; also on sheet 15 20 21 25
N9967323: Q3.D(DRAIN) ; also on sheet 15 20 21 25
N9967336: Q1.D(DRAIN) ; also on sheet 15 20 21 25
N9967965: J3.4(TMS) J11.4(TMS) R147.2 U28.6(1A1) ; also on sheet 25
N9967983: J3.10(TDI) J11.10(TDI) R148.2 U28.8(2A1) ; also on sheet 25
N9967995: J3.8(TDO) J11.8(TDO) R145.2 U25.R7(TDO_0) ; also on sheet 25
N9968007: J3.6(TCK) J11.6(TCK) R146.2 U28.7(1A2) ; also on sheet 25
N9997340: DS3.A(ANODE) R153.2 S1.10(B1) U25.J7(DONE_0) ; also on sheet 14

Not connected (* = marked no-connect by the designer): J3 12(VPGR)* 14(INIT)*; J11 12(VPGR)* 14(INIT)*; SW1 1(3) 4; T1 2*; T2 2*; T3 2*; T4 2*; T9 2*; T10 2*; T11 2*; T12 2*; U25 AA5(IO_L15P_T2_DQS_34) AA9(IO_L11P_T1_SRCC_33) AA10(IO_L14P_T2_SRCC_33) AA18(IO_L11N_T1_SRCC_32) AB1(IO_L9P_T1_DQS_34) AB2(IO_L11P_T1_SRCC_34) AB5(IO_L15N_T2_DQS_34) AB6(IO_L16P_T2_34) AB7(IO_L10P_T1_33) AB9(IO_L11N_T1_SRCC_33) AB10(IO_L14N_T2_SRCC_33) AB14(IO_L10P_T1_32) AB15(IO_L10N_T1_32) AB17(IO_L14P_T2_SRCC_32) AC1(IO_L9N_T1_DQS_34) AC2(IO_L11N_T1_SRCC_34) AC3(IO_L14N_T2_SRCC_34) AC4(IO_L14P_T2_SRCC_34) AC6(IO_L16N_T2_34) AC7(IO_L10N_T1_33) AC13(IO_L17P_T2_33) AC17(IO_L14N_T2_SRCC_32) AC19(IO_L17P_T2_32) AD1(IO_L20P_T3_34) AD10(IO_L20P_T3_33) AD11(IO_L19P_T3_33) AD13(IO_L17N_T2_33) AD16(IO_L6P_T0_32) AD19(IO_L17N_T2_32) AD20(IO_L15P_T2_DQS_32) AE1(IO_L20N_T3_34) AE2(IO_L22N_T3_34) AE6(IO_L23P_T3_34) AE7(IO_L7P_T1_33) AE10(IO_L20N_T3_33) AE11(IO_L19N_T3_VREF_33) AE12(IO_L21P_T3_DQS_33) AE13(IO_L23P_T3_33) AE16(IO_L6N_T0_VREF_32) AE17(IO_L1P_T0_32) AE20(IO_L15N_T2_DQS_32) AF4(IO_L21N_T3_DQS_34) AF5(IO_L21P_T3_DQS_34) AF7(IO_L7N_T1_33) AF8(IO_L22N_T3_33) AF12(IO_L21N_T3_DQS_33) AF17(IO_L1N_T0_32) M11(GNDADC_0) M12(VCCADC_0) N11(VREFN_0) N12(VP_0) P11(VN_0) P12(VREFP_0) T7(IO_25_VRP_34) U4(IO_0_VRN_34) U5(IO_L1N_T0_34) U6(IO_L1P_T0_34) U9(IO_0_VRN_33) V4(IO_L6P_T0_34) V9(IO_L6P_T0_33) V11(IO_L1P_T0_33) V12(IO_25_VRP_33) V16(IO_L20P_T3_32) V17(IO_L20N_T3_32) V18(IO_L23P_T3_32) W1(IO_L10P_T1_34) W4(IO_L6N_T0_VREF_34) W8(IO_L6N_T0_VREF_33) W11(IO_L1N_T0_33) W16(IO_L22N_T3_32) W18(IO_L21P_T3_DQS_32) W19(IO_L21N_T3_DQS_32) Y1(IO_L10N_T1_34) Y5(IO_L17N_T2_34) Y6(IO_L17P_T2_34) Y12(IO_L18N_T2_33) Y13(IO_L18P_T2_33) Y15(IO_L9P_T1_DQS_32) Y16(IO_L9N_T1_DQS_32) Y17(IO_L19P_T3_32) Y18(IO_L19N_T3_VREF_32); U26 6(Y0)

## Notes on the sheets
sheet 1
- Uses Xilinx Kintex XC7K160T-2FFG676
- Sheet 7
- Sheet 23
- BANK 0
- Sheet 11
- BOARDLAYOUT also
  includes a list
  of design
  changes.
- Contains JTAG Connectors
- Contains SPI Flash for storing the personality
- Sheet 14
- BANK 12
- High Range
- BANK 115
- BANK 16
- High Range
- GTX
- BANK 15
- BANK 13
- High Range
- BANK 116
- GTX
- Sheet 12
- High Range
- BANK 14
- High Range
- Sheet 13
- Contains 2 SFP+ Connectors
- Hooking power to the FPGA
- Contains Clocks and LEDs
- Contains USB Interface
- Sheet 5
- BANK 32
- High Precision
- BANK 33
- High Precision
- BANK 34
- High Precision
- Sheet 10
- Contains ZDOK Connector, 1PPS Connector
- Contains Clock Generator Synthesizer
- Sheet 6
- Contains the Raspberry Pi Interface
- Contains the 3 ADCs
- Sheet 9
- REV C CONTAINS CHANGES FOR THE
  SECOND VERSION OF THE BOARD.
- Contains DC-DC Converters
sheet 2
- MO is 1 for SPI mode
- See Sheet 27 of the KC705 Schematic
- Connect  A to Y0 and Y1 when S=1
- Digikey 296-15568-1-nd
- M[2:0] Determines the configuration mode.
- See Sheet 27 of the KC705 Schematic
- BANK 0
- Digikey CKN6074-ND
- See Sheet 3 of the KC705 Schematic
- Configuration Clock to SPI Memory
- SPI Select Switch
- ON = SPI Divide
- OFF = SPI External
- FPGA_PROG_B from header for
  external programming
- FPGA_INIT_B can be switched to FPGA_DONE
- TDO not buffered here to conform with KC705 design
- DNP - Do Not Populate
- See Sheet 3 of the KC705 Schematic
- Scatter ground test points around the board.
  A pin can be soldered in for a scope ground.
- Change Levels from
  3.3V to 2.5V
- Level shift to 3.3V then to PI.
- From Raspberry Pi or External Header
- For
  monitoring
  Xilinx
  temperature
- Vertical pins for board interior Digikey WM17469-ND
- Right angle pins for board edge Digikey WM18863-ND
- For use with Digilent JTAG USB Cable Part#250-003P
- J3 & J11 changed to industry standard format connectors for Rev B
sheet 3
- From 3.3V with series/parallel divider.
- High Performance
- Used for DDR on sheet 3 of KC705
- XC7K160T-2FFG676
- Gets VCCO from VCCO1V8
- PMBUS
  Level-Shifter
- ADC OUT PINS are placed so that pairs of differential
  pairs are close to each other for timing purposes.
- From Xilinx, 1.8-volt logic
- High Performance
- Contains U2 in Sheet 2
- LVDS Outputs
- Even numbers are P, odd N
- See Sheet 7 of
  KC705
- Gets VCCO from VCCO1V8
- From Clock Generators
- Contains U7 in Sheet 3
- High Performance
- Could possibly have clocks from one
  ADC provide the clocks for all 3.
- SRCC are single region clocks
- Could then not hook up the clocks
  from the other 2.
- MRCC are multi region clocks
- Contains U12 in Sheet 4
- A compromise could be to hook up
  2 of the 3 clocks.
- See UG471 Series_Select IO for info on
  SERDES clocking.
- See Sheet 8 of KC705
- Gets VCCO from VCCO1V8
- Can use slide on SMA Emerson 142-0701-801
- Short wires from SMA
  Connectors on box soldered
  to this TP.
sheet 4
- Note 1:  Components associated with ADC inputs IP1 and IP3 are on the top side of the board.
           Components associated with IP2 and IP4 are on the bottom side of the board.
- From Xilinx, 1.8-volt logic
- Note 2: Layout the board such that the attenuators can be replaced by 0402 zero ohm jumpers.
- Maximum Digital
  Input Voltage of
  3.9V
- Note 2
- Digikey 1127-1648-ND
- Note 1
- LVDS to Xilinx
- From SMA connectors
- LVDS to Xilinx
- I = 435 ma (counting LVDS outptuts)
- From linear regulator LP3856
- pin 1
- From linear regulator LP3856
- pin 36
- rev 2014-2-4: Change 3db pad vendor.  Change analog terms.
- rev 2014-1-29: Add 3db pads to inputs for matching
- rev 2013-11-14: update to 5/28/2013 Berkeley version:
                  change xformer type and AC coupled xformer.
                  Also update to preferred values for input terminations
- rev 2014-1-3: fix typo in notes
- U1, pin 32
- rev 2013-10-23: Add to/from notes for I/O.
                  Change name and symbol for power
- rev 2013-10-27: Show ADC data outputs as bus to simplify high level view.
                  Eliminate 0.1 uF cap on CLK_IN_P/N
- rev 2014-5-14:  Add PU and PDs to PD and RSTN.
- From Clock Generator
  LVPECL input, capacitively coupled
- Change name of DVDD & OVDD to VDDO & VDDD
sheet 5
- Note 1:  Components associated with ADC inputs IP1 and IP3 are on the top side of the board.
           Components associated with IP2 and IP4 are on the bottom side of the board.
- From Xilinx, 1.8-volt logic
- Note 2: Layout the board such that the attenuators can be replaced by 0402 zero ohm jumpers.
- Maximum Digital
  Input Voltage of
  3.9V
- Note 2
- Digikey 1127-1648-ND
- Note 1
- LVDS to Xilinx
- From SMA connectors
- LVDS to Xilinx
- I = 435 ma (counting LVDS outptuts)
- From linear regulator LP3856
- pin 1
- From linear regulator LP3856
- pin 36
- rev 2014-2-4: Change 3db pad vendor.  Change analog terms.
- rev 2014-1-29: Add 3db pads to inputs for matching
- rev 2013-11-14: update to 5/28/2013 Berkeley version:
                  change xformer type and AC coupled xformer.
                  Also update to preferred values for input terminations
- rev 2014-1-3: fix typo in notes
- U1, pin 32
- rev 2013-10-23: Add to/from notes for I/O.
                  Change name and symbol for power
- rev 2013-10-27: Show ADC data outputs as bus to simplify high level view.
                  Eliminate 0.1 uF cap on CLK_IN_P/N
- rev 2014-5-14:  Add PU and PDs to PD and RSTN.
- From Clock Generator
  LVPECL input, capacitively coupled
- Change name of DVDD & OVDD to VDDO & VDDD
